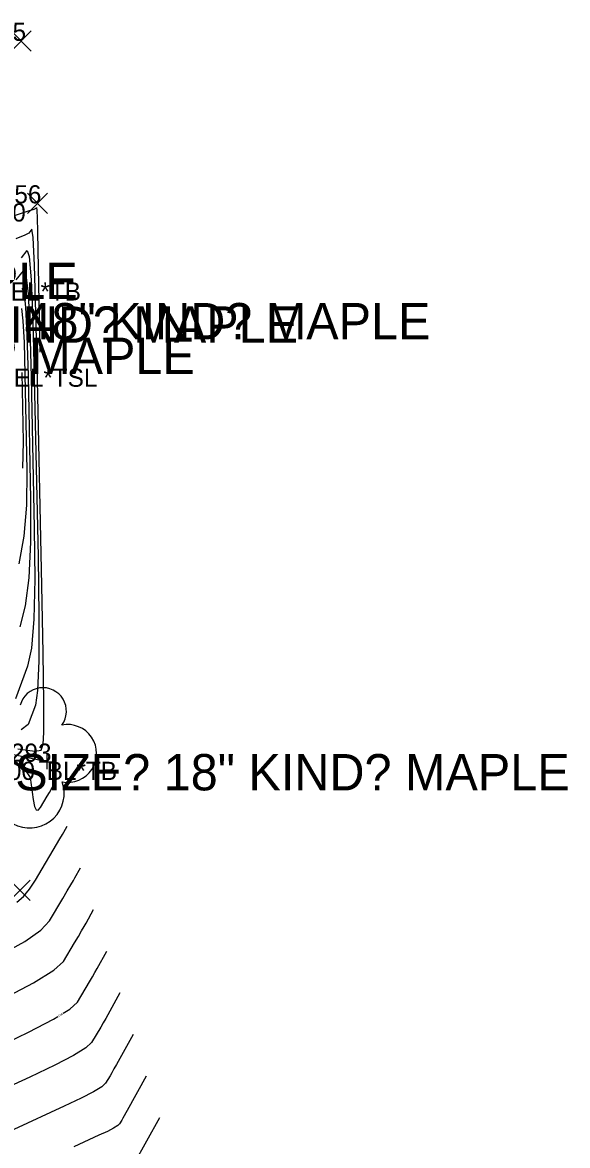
# Model space of a CAD drawing. Extents: x 1654928 to 1810050, y 486881 to 626330.
# Drawn here: x 1801558.3 to 1801594.3, y 489797.4 to 489871.6 of the extents above; entities that cross this region are included whole.
import ezdxf

# ---------------------------------------------------------------- set-up
doc = ezdxf.new("R2010")
doc.units = 0
for name, color, linetype in [('DT_X_Contour_Major', 7, 'Continuous'), ('DT_X_Contour_Minor', 7, 'Continuous'), ('SV_X_Random_Point', 7, 'Continuous'), ('SV_X_Shot_Marker', 7, 'Continuous'), ('SV_X_Text_Comment', 7, 'Continuous'), ('SV_X_Text_Elevation', 7, 'Continuous'), ('SV_X_Text_Name', 7, 'Continuous'), ('SV_X_Top_of_Bank', 7, 'Continuous'), ('VG_X_Cells', 7, 'Continuous'), ('VG_X_Text', 7, 'Continuous')]:
    doc.layers.add(name, color=color, linetype=linetype)

msp = doc.modelspace()

# ---------------------------------------------------------------- linework, layer by layer
at = {"layer": 'DT_X_Contour_Major'}
for points in [[(1801557.849, 489854.553), (1801558.322, 489855.161), (1801558.487, 489854.892), (1801558.627, 489853.632), (1801558.742, 489851.379), (1801558.832, 489848.134), (1801559.038, 489838.157), (1801559.069, 489834.782), (1801559.004, 489832.138), (1801558.845, 489830.226), (1801558.591, 489829.045), (1801557.789, 489826.872)], [(1801556.856, 489809.993), (1801558.409, 489810.856), (1801559.472, 489811.594), (1801560.045, 489812.209), (1801560.919, 489813.683), (1801561.215, 489814.184), (1801561.449, 489814.581), (1801561.62, 489814.875), (1801561.727, 489815.064), (1801562.084, 489815.709)], [(1801566.44, 489801.958), (1801565.179, 489799.682), (1801564.898, 489799.181), (1801564.822, 489799.049), (1801564.677, 489798.803), (1801564.55, 489798.687), (1801564.281, 489798.522), (1801563.868, 489798.308), (1801563.313, 489798.045), (1801561.64, 489797.279)]]:
    msp.add_lwpolyline(points, dxfattribs=at)
at = {"layer": 'DT_X_Contour_Minor'}
for points in [[(1801548.311, 489862.632), (1801550.187, 489860.326), (1801551.415, 489859.003), (1801552.567, 489858.145), (1801553.643, 489857.752), (1801554.643, 489857.825), (1801557.207, 489858.638), (1801558.05, 489858.907), (1801558.656, 489859.104), (1801559.025, 489859.229), (1801559.156, 489859.282), (1801559.191, 489859.326), (1801559.206, 489859.16), (1801559.225, 489858.631), (1801559.248, 489857.739), (1801559.276, 489856.483), (1801559.415, 489849.772)], [(1801557.944, 489823.567), (1801559.07, 489823.43), (1801559.482, 489823.484), (1801559.629, 489823.883), (1801559.664, 489824.65), (1801559.659, 489826.652), (1801559.614, 489829.889), (1801559.529, 489834.361), (1801559.247, 489847.933), (1801559.146, 489852.373), (1801559.051, 489855.517), (1801558.963, 489857.363), (1801558.882, 489857.913), (1801558.675, 489857.648), (1801558.42, 489857.501), (1801557.809, 489857.26)], [(1801558.195, 489856.014), (1801558.573, 489856.499), (1801558.708, 489856.107), (1801558.831, 489854.565), (1801558.942, 489851.874), (1801559.04, 489848.033), (1801559.284, 489836.259), (1801559.341, 489832.335), (1801559.332, 489829.395), (1801559.255, 489827.438), (1801559.11, 489826.464), (1801558.635, 489825.178), (1801558.163, 489824.823)], [(1801558.206, 489853.995), (1801558.341, 489853.775), (1801558.456, 489852.741), (1801558.55, 489850.895), (1801558.624, 489848.234), (1801558.793, 489840.055), (1801558.796, 489837.228), (1801558.677, 489834.881), (1801558.436, 489833.014), (1801558.073, 489831.626)], [(1801558.195, 489852.658), (1801558.285, 489851.851), (1801558.358, 489850.41), (1801558.416, 489848.335), (1801558.548, 489841.953), (1801558.523, 489839.675), (1801558.349, 489837.624), (1801558.026, 489835.802)], [(1801558.208, 489848.435), (1801558.303, 489843.852), (1801558.25, 489842.121)], [(1801557.514, 489822.737), (1801558.419, 489822.214), (1801558.77, 489821.676), (1801558.967, 489820.219), (1801559.053, 489819.776), (1801559.162, 489819.541), (1801559.294, 489819.513), (1801559.45, 489819.692), (1801559.897, 489820.445), (1801560.045, 489820.696), (1801560.156, 489820.884), (1801560.229, 489821.009), (1801560.342, 489821.209)], [(1801557.887, 489813.445), (1801558.316, 489813.818), (1801558.727, 489814.299), (1801559.119, 489814.89), (1801560.735, 489817.619), (1801560.908, 489817.913), (1801560.996, 489818.067), (1801561.213, 489818.459)], [(1801548.648, 489803.213), (1801554.153, 489805.734), (1801556.931, 489807.048), (1801558.994, 489808.119), (1801560.34, 489808.945), (1801560.971, 489809.528), (1801561.7, 489810.756), (1801561.952, 489811.183), (1801562.163, 489811.543), (1801562.331, 489811.836), (1801562.459, 489812.062), (1801562.955, 489812.959)], [(1801560.946, 489806.106), (1801561.393, 489806.381), (1801561.898, 489806.847), (1801562.689, 489808.183), (1801562.876, 489808.505), (1801563.043, 489808.797), (1801563.19, 489809.059), (1801563.826, 489810.208)], [(1801564.697, 489807.458), (1801563.755, 489805.759), (1801563.59, 489805.467), (1801563.425, 489805.182), (1801562.824, 489804.166), (1801562.445, 489803.816), (1801561.637, 489803.32), (1801560.4, 489802.678), (1801558.733, 489801.889), (1801553.715, 489799.592), (1801551.957, 489798.55), (1801550.444, 489797.149)], [(1801544.46, 489797.085), (1801545.728, 489798.354), (1801547.492, 489799.575), (1801549.753, 489800.748), (1801556.443, 489803.812), (1801558.666, 489804.863), (1801560.316, 489805.719), (1801560.588, 489805.887)], [(1801565.569, 489804.708), (1801564.467, 489802.72), (1801564.304, 489802.429), (1801564.162, 489802.181), (1801564.042, 489801.976), (1801563.75, 489801.484), (1801563.498, 489801.251), (1801562.959, 489800.921), (1801562.134, 489800.493), (1801561.023, 489799.967), (1801557.678, 489798.435), (1801556.439, 489797.57), (1801555.231, 489796.125)], [(1801567.311, 489799.208), (1801565.603, 489796.122)]]:
    msp.add_lwpolyline(points, dxfattribs=at)
at = {"layer": 'SV_X_Random_Point'}
for p, q in [((1801557.5, 489869.672), (1801558.833, 489871.007)), ((1801557.5, 489871.007), (1801558.833, 489869.672)), ((1801558.586, 489858.941), (1801559.919, 489860.276)), ((1801558.586, 489860.276), (1801559.919, 489858.941)), ((1801557.429, 489813.557), (1801558.762, 489814.892)), ((1801557.429, 489814.892), (1801558.762, 489813.557))]:
    msp.add_line(p, q, dxfattribs=at)
at = {"layer": 'SV_X_Shot_Marker'}
for p, q in [((1801559.863, 489823.221), (1801559.863, 489822.221)), ((1801559.363, 489822.721), (1801560.363, 489822.721)), ((1801559.863, 489822.721), (1801559.863, 489822.721))]:
    msp.add_line(p, q, dxfattribs=at)
at = {"layer": 'SV_X_Top_of_Bank'}
msp.add_lwpolyline([(1801559.863, 489822.721), (1801539.336, 489827.057), (1801528.648, 489823.028), (1801533.885, 489825.215), (1801524.048, 489823.1), (1801504.227, 489821.976), (1801498.255, 489815.137), (1801490.955, 489811.4), (1801479.493, 489812.14), (1801473.308, 489811.885), (1801466.247, 489811.095)], dxfattribs=at)
at = {"layer": 'VG_X_Cells'}
for centre, radius, start, end in [((1801559.607, 489826.06), 1.553, 323.82996, 165.0376), ((1801561.241, 489823.267), 1.915, 259.14531, 101.45961), ((1801558.727, 489820.626), 2.284, 184.94757, 19.45715)]:
    msp.add_arc(centre, radius, start, end, dxfattribs=at)

# ---------------------------------------------------------------- texts
at = {"layer": 'DT_X_Contour_Minor'}
msp.add_text('852', height=0.14, rotation=211.53531, dxfattribs=at).set_placement((1801560.866, 489806.139))
at = {"layer": 'SV_X_Text_Comment'}
for s, p in [('EL*TB', (1801557.484, 489853.19)), ('EL*TSL', (1801557.678, 489847.492)), ('BL*TB', (1801559.863, 489821.521))]:
    msp.add_text(s, height=1.2, dxfattribs=at).set_placement(p)
at = {"layer": 'SV_X_Text_Elevation'}
for s, p in [('851.6400', (1801551.78, 489858.408)), ('851.4900', (1801552.39, 489821.521))]:
    msp.add_text(s, height=1.2, dxfattribs=at).set_placement(p)
at = {"layer": 'SV_X_Text_Name'}
for s, p in [('JMR1255', (1801551.629, 489870.34)), ('JMR1256', (1801552.639, 489859.608)), ('JMR1293', (1801553.306, 489822.721))]:
    msp.add_text(s, height=1.2, dxfattribs=at).set_placement(p)
at = {"layer": 'VG_X_Text'}
for s, p in [('SIZE? 18" KIND? MAPLE', (1801525.28, 489853.28)), ('SIZE? 24" KIND? MAPLE', (1801539.835, 489850.403)), ('SIZE? 48" KIND? MAPLE', (1801548.581, 489850.625)), ('SIZE? 24" KIND? MAPLE', (1801533.011, 489848.335)), ('SIZE? 18" KIND? MAPLE', (1801557.78, 489820.831))]:
    msp.add_text(s, height=2.4, dxfattribs=at).set_placement(p)

doc.saveas('drawing.dxf')
